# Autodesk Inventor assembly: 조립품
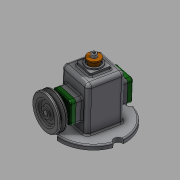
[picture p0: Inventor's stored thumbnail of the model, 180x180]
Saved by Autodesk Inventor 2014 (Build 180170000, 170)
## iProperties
Created: 2018-07
Part Number: 조립품
Document SubType Name: Assembly
Designer: user
Author: user
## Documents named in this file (16)
- C:\Users\user\Desktop\480708V1003\조립품.iam
- C:\Users\user\Desktop\480708V1003\V벨트풀리.ipt
- C:\Users\user\Desktop\480708V1003\고정핀 1.2x8.ipt
- C:\Users\user\Desktop\480708V1003\뒤커버.ipt
- C:\Users\user\Desktop\480708V1003\링크.ipt
- C:\Users\user\Desktop\480708V1003\멈춤나사 M3x8.ipt
- C:\Users\user\Desktop\480708V1003\베어링 12x32x10.ipt
- C:\Users\user\Desktop\480708V1003\본체.ipt
- C:\Users\user\Desktop\480708V1003\볼트 M4.ipt
- C:\Users\user\Desktop\480708V1003\부시.ipt
- C:\Users\user\Desktop\480708V1003\슬라이드.ipt
- C:\Users\user\Desktop\480708V1003\앞커버.ipt
- C:\Users\user\Desktop\480708V1003\오일 실 12 25 7.ipt
- C:\Users\user\Desktop\480708V1003\키 4x4x10.ipt
- C:\Users\user\Desktop\480708V1003\편심축.ipt
- C:\Users\user\Desktop\480708V1003\핀 5x18.ipt
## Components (3 placed, 3 different names)
1. V벨트풀리:1 — Mate:15, Flush:1, Mate:16, Mate:29
2. 고정핀 1.2x8:1 — Mate:31
3. 핀 5x18:1 — Mate:26, Mate:27, Mate:31, Angle:1
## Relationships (8: Mate 6, Flush 1, Angle 1)
- Mate:15: V벨트풀리:1
- Flush:1: V벨트풀리:1
- Mate:16: V벨트풀리:1
- Mate:26: 핀 5x18:1
- Mate:27: 핀 5x18:1
- Mate:29: V벨트풀리:1
- Mate:31: 고정핀 1.2x8:1 ↔ 핀 5x18:1
- Angle:1: 핀 5x18:1
